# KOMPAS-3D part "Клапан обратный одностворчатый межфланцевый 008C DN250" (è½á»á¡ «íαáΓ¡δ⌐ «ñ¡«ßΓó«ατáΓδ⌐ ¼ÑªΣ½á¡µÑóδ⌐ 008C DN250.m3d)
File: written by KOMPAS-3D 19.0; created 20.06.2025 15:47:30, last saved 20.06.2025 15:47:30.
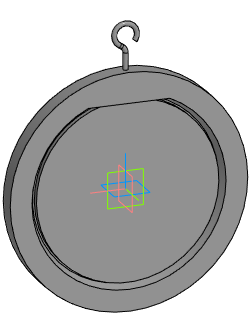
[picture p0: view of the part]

Document properties: Полное имя файла: E:\Dendor Работа Сачек\3D для проектировщиков\5.1 Тип 008C. Клапан обратный одностворчатый межфланцевый\stp_Клапан обратный одностворчатый межфланцевый 008C\Клапан обратный одностворчатый межфланцевый 008C DN250.m3d

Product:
- Part/product: Клапан обратный одностворчатый межфланцевый 008C DN250

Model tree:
1. Операция без истории:1  (labels: Клапан обратный одностворчатый межфланцевый 008C DN250)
